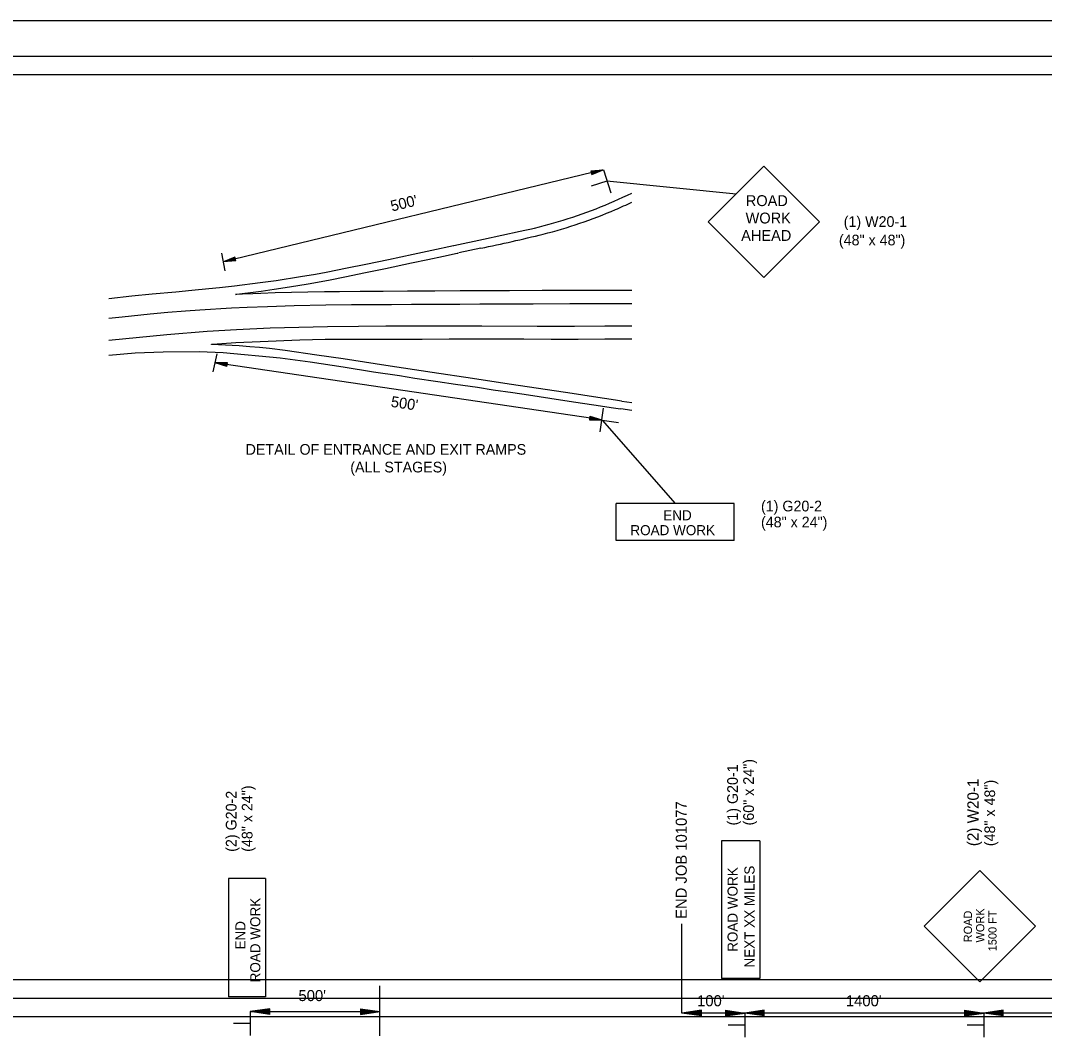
# Model space of a CAD drawing. Extents: x 13528 to 25043, y 7635 to 10612.
# Drawn here: x 14107 to 14665, y 10057 to 10612 of the extents above; entities that cross this region are included whole.
import ezdxf

# ---------------------------------------------------------------- set-up
doc = ezdxf.new("R2010")
doc.units = 0
for name, color, linetype in [('Default', 7, 'Continuous'), ('R_Border', 7, 'Continuous'), ('R_Border Plan-Plan', 7, 'Continuous'), ('R_Border Title', 7, 'Continuous'), ('R_Draft', 7, 'Continuous'), ('R_No Plot', 7, 'Continuous'), ('R_Revision Date Text', 7, 'Continuous')]:
    doc.layers.add(name, color=color, linetype=linetype)

msp = doc.modelspace()

# ---------------------------------------------------------------- linework, layer by layer
at = {"layer": 'Default'}
for p, q in [((14496.62, 10516.89), (14426.18, 10523.85)), ((14423.6, 10393.7), (14463.38, 10348.28)), ((14467.07, 10070.37), (14467.07, 10118.93)), ((14302.47, 10057.91), (14302.47, 10085.27)), ((14231.83, 10071.14), (14302.45, 10071.14)), ((14501.38, 10070.37), (14467.07, 10070.37)), ((14631.67, 10070.37), (14501.38, 10070.37)), ((14722.64, 10070.37), (14631.67, 10070.37))]:
    msp.add_line(p, q, dxfattribs=at)
for points in [[(14342.84, 10488.87), (14359.01, 10492.27), (14378.86, 10496.59)], [(14154.77, 10460.04), (14167.3, 10461.45), (14178.38, 10462.52), (14191.29, 10463.65), (14200.02, 10464.43), (14209.16, 10465.34), (14215.1, 10465.98), (14223.19, 10466.91), (14237.22, 10468.67), (14245.94, 10469.84), (14259.16, 10471.87), (14267.31, 10473.25), (14273.11, 10474.38), (14284.68, 10476.61), (14294.88, 10478.74), (14307.2, 10481.3), (14320.55, 10484.11), (14330.83, 10486.33), (14342.56, 10488.79)], [(14439.75, 10464.37), (14434.31, 10464.37), (14417.92, 10464.32), (14405.38, 10464.29), (14390.88, 10464.27), (14373.12, 10464.2), (14359.89, 10464.16), (14346.18, 10464.12), (14332.37, 10464.05), (14317.44, 10463.92), (14304.24, 10463.86), (14291.73, 10463.72), (14280.35, 10463.61), (14272.2, 10463.54), (14263.22, 10463.41), (14254.23, 10463.25), (14245.3, 10462.99), (14237.53, 10462.73), (14233.25, 10462.56), (14227.52, 10462.33), (14224.49, 10462.15), (14223.75, 10462.14), (14224.43, 10462.25), (14227.45, 10462.6), (14233.3, 10463.35), (14237.77, 10463.94), (14244.83, 10464.98), (14253.27, 10466.28), (14263.28, 10467.91), (14274.53, 10469.99), (14284.27, 10471.92), (14293.71, 10473.9), (14305.53, 10476.39), (14319.71, 10479.36), (14328.64, 10481.22), (14337.04, 10482.99), (14344.62, 10484.6), (14345.2, 10484.76)], [(14357.47, 10487.33), (14345.44, 10484.79)], [(14154.77, 10449.2), (14162.05, 10450.05), (14177.18, 10451.59), (14186.79, 10452.52), (14196.43, 10453.28), (14204.28, 10453.84), (14221.51, 10454.93), (14230.16, 10455.31), (14241.15, 10455.68), (14255.64, 10456.08), (14272.99, 10456.44), (14286.93, 10456.62), (14296.13, 10456.68), (14308.85, 10456.78), (14319.63, 10456.85), (14335.14, 10456.92), (14346, 10456.96), (14356.88, 10457.03), (14369.13, 10457.08), (14386.07, 10457.13), (14405.94, 10457.17), (14419.19, 10457.23), (14433.73, 10457.25), (14439.75, 10457.25)], [(14154.77, 10437.25), (14186.34, 10440.35), (14208.4, 10442.08), (14224.32, 10443.08), (14242.6, 10443.93), (14273.89, 10444.78), (14290.86, 10444.93), (14305.62, 10445), (14330.83, 10444.98), (14357.96, 10444.97), (14388.23, 10444.92), (14408.52, 10444.95), (14425.09, 10444.99), (14439.75, 10445)], [(14434.23, 10404.07), (14430.9, 10404.59), (14418.8, 10406.42), (14407.22, 10408.2), (14388.94, 10410.92), (14372.87, 10413.3), (14353.01, 10416.3), (14330.93, 10419.53), (14305.77, 10423.38), (14282.39, 10427.05), (14268.02, 10429.1), (14250.82, 10431.67), (14242.33, 10432.64), (14236.86, 10433.16), (14231.58, 10433.63), (14225.7, 10434.08), (14214.52, 10434.79), (14210.74, 10434.97), (14210.7, 10435.05), (14213.8, 10435.32), (14223.99, 10435.92), (14237.11, 10436.56), (14258.88, 10437.43), (14272.67, 10437.7), (14293.19, 10437.81), (14309.43, 10437.8), (14325.56, 10437.84), (14340.29, 10437.93), (14352.22, 10437.94), (14367.06, 10437.9), (14380.87, 10437.93), (14395.78, 10437.87), (14410.45, 10437.86), (14425.12, 10437.92), (14438.03, 10437.93), (14439.75, 10437.94)], [(14154.77, 10429.04), (14169.05, 10430.26), (14184.4, 10430.9), (14203.93, 10431.01), (14216.99, 10430.59), (14248.04, 10427.67), (14264.36, 10425.35), (14282.44, 10422.62), (14299.03, 10420.05), (14313.06, 10417.91), (14321.42, 10416.6), (14334.07, 10414.67), (14343.69, 10413.31), (14355.67, 10411.53), (14364.27, 10410.24), (14374.97, 10408.64), (14383.4, 10407.37), (14395.06, 10405.59), (14407.96, 10403.67), (14419.1, 10402), (14429.83, 10400.37), (14433.62, 10399.81)], [(14434.35, 10404.05), (14439.75, 10403.22)], [(14439.75, 10398.87), (14433.78, 10399.76)]]:
    msp.add_lwpolyline(points, dxfattribs=at)
for centre, major_axis, ratio, start_param, end_param in [((14299.19, 10813.8), (136.7, 298.37), 0.999173, 3.949784, 4.014407), ((14307.26, 10794.21), (311.69, 3.76), 0.99865, 5.108014, 5.139342), ((14324.08, 10755.04), (261.63, 48.54), 0.992861, 4.737589, 4.90036), ((14328.05, 10745.09), (257.87, 23.44), 0.996093, 4.869476, 5.030314), ((14159.01, 11428.79), (966.83, 149.44), 0.983429, 4.765892, 4.801526)]:
    msp.add_ellipse(centre, major_axis=major_axis, ratio=ratio, start_param=start_param, end_param=end_param, dxfattribs=at)
at = {"layer": 'R_Border'}
for p, q in [((14424.19, 10530.14), (14217.16, 10479.87)), ((14417.46, 10529.53), (14424.19, 10530.14)), ((14417.46, 10529.53), (14417.94, 10527.59)), ((14417.5, 10529.37), (14423.1, 10529.87)), ((14417.54, 10529.21), (14421.99, 10529.6)), ((14417.58, 10529.04), (14420.91, 10529.34)), ((14417.62, 10528.88), (14419.81, 10529.07)), ((14417.66, 10528.71), (14418.73, 10528.81)), ((14417.74, 10528.41), (14418.73, 10528.81)), ((14417.78, 10528.24), (14419.81, 10529.07)), ((14417.82, 10528.08), (14420.91, 10529.34)), ((14417.86, 10527.92), (14421.99, 10529.6)), ((14417.9, 10527.75), (14423.1, 10529.87)), ((14417.94, 10527.59), (14424.19, 10530.14)), ((14424.37, 10530.11), (14428.36, 10517.64)), ((14481.47, 10501.74), (14511.78, 10532.05)), ((14511.78, 10532.05), (14542.09, 10501.74)), ((14426.18, 10523.85), (14417.66, 10521.13)), ((14481.47, 10501.74), (14511.78, 10471.46)), ((14511.78, 10471.46), (14542.09, 10501.74)), ((14218.05, 10475.01), (14216.28, 10484.74)), ((14223.41, 10482.42), (14217.16, 10479.87)), ((14223.45, 10482.26), (14218.25, 10480.14)), ((14223.89, 10480.48), (14223.41, 10482.42)), ((14223.89, 10480.48), (14217.16, 10479.87)), ((14223.85, 10480.64), (14218.25, 10480.14)), ((14223.49, 10482.09), (14219.36, 10480.41)), ((14223.81, 10480.8), (14219.36, 10480.41)), ((14223.53, 10481.93), (14220.44, 10480.67)), ((14223.77, 10480.97), (14220.44, 10480.67)), ((14223.57, 10481.77), (14221.54, 10480.94)), ((14223.73, 10481.13), (14221.54, 10480.94)), ((14223.61, 10481.6), (14222.63, 10481.2)), ((14223.69, 10481.3), (14222.63, 10481.2)), ((14211.66, 10420.04), (14213.67, 10429.72)), ((14219.41, 10424.89), (14212.66, 10424.88)), ((14423.42, 10393.76), (14212.66, 10424.88)), ((14219.12, 10422.91), (14212.66, 10424.88)), ((14219.39, 10424.73), (14213.77, 10424.71)), ((14219.14, 10423.08), (14213.77, 10424.71)), ((14219.36, 10424.56), (14214.9, 10424.55)), ((14219.17, 10423.25), (14214.9, 10424.55)), ((14219.34, 10424.39), (14216, 10424.38)), ((14219.19, 10423.41), (14216, 10424.38)), ((14219.31, 10424.23), (14217.12, 10424.22)), ((14219.22, 10423.58), (14217.12, 10424.22)), ((14219.29, 10424.06), (14218.22, 10424.06)), ((14219.24, 10423.75), (14218.22, 10424.06)), ((14219.12, 10422.91), (14219.41, 10424.89)), ((14422.48, 10387.29), (14424.35, 10400.24)), ((14416.96, 10395.73), (14416.67, 10393.75)), ((14416.67, 10393.75), (14423.42, 10393.76)), ((14416.69, 10393.91), (14422.31, 10393.93)), ((14416.72, 10394.08), (14421.18, 10394.09)), ((14416.74, 10394.25), (14420.08, 10394.26)), ((14416.76, 10394.42), (14418.96, 10394.42)), ((14416.79, 10394.58), (14417.86, 10394.58)), ((14416.84, 10394.89), (14417.86, 10394.58)), ((14416.86, 10395.06), (14418.96, 10394.42)), ((14416.89, 10395.23), (14420.08, 10394.26)), ((14416.91, 10395.4), (14421.18, 10394.09)), ((14416.93, 10395.56), (14422.31, 10393.93)), ((14416.96, 10395.73), (14423.42, 10393.76)), ((14423.6, 10393.7), (14432.44, 10392.44)), ((14495.56, 10348.28), (14431.2, 10348.28)), ((14431.2, 10328.06), (14431.2, 10348.28)), ((14495.56, 10328.06), (14495.56, 10348.28)), ((14495.56, 10328.06), (14431.2, 10328.06)), ((14629.5, 10148.02), (14599.19, 10117.72)), ((14629.5, 10148.02), (14659.78, 10117.72)), ((14219.91, 10143.66), (14219.91, 10079.3)), ((14240.13, 10143.66), (14219.91, 10143.66)), ((14240.13, 10143.66), (14240.13, 10079.3)), ((14599.19, 10117.72), (14629.5, 10087.41)), ((14659.78, 10117.72), (14629.5, 10087.41)), ((14240.13, 10079.3), (14219.91, 10079.3)), ((14231.83, 10071.14), (14231.83, 10058.05)), ((14501.38, 10070.37), (14501.38, 10057.28)), ((14631.67, 10070.37), (14631.67, 10057.28)), ((14231.64, 10064.63), (14222.7, 10064.62)), ((14501.19, 10063.86), (14492.25, 10063.86)), ((14631.48, 10063.86), (14622.54, 10063.86))]:
    msp.add_line(p, q, dxfattribs=at)
at = {"layer": 'R_Border Plan-Plan'}
msp.add_line((13590.22, 10078.42), (15171.12, 10078.42), dxfattribs=at)
at = {"layer": 'R_Border Title'}
for p, q in [((14242.42, 10072.73), (14231.83, 10071.14)), ((14242.42, 10069.55), (14231.83, 10071.14)), ((14242.42, 10072.46), (14233.6, 10071.14)), ((14242.42, 10069.81), (14233.6, 10071.14)), ((14242.42, 10072.19), (14235.42, 10071.14)), ((14242.42, 10070.08), (14235.42, 10071.14)), ((14242.42, 10071.93), (14237.18, 10071.14)), ((14242.42, 10070.35), (14237.18, 10071.14)), ((14242.42, 10071.66), (14238.98, 10071.14)), ((14242.42, 10070.62), (14238.98, 10071.14)), ((14242.42, 10071.39), (14240.75, 10071.14)), ((14242.42, 10070.89), (14240.75, 10071.14)), ((14242.42, 10069.55), (14242.42, 10072.73)), ((14291.86, 10072.73), (14302.45, 10071.14)), ((14291.86, 10072.73), (14291.86, 10069.55)), ((14291.86, 10072.46), (14300.69, 10071.14)), ((14291.86, 10072.19), (14298.86, 10071.14)), ((14291.86, 10071.93), (14297.1, 10071.14)), ((14291.86, 10071.65), (14295.3, 10071.14)), ((14291.86, 10071.39), (14293.53, 10071.14)), ((14291.86, 10069.55), (14302.45, 10071.14)), ((14291.86, 10070.62), (14295.3, 10071.14)), ((14291.86, 10070.08), (14298.86, 10071.14)), ((14291.86, 10069.81), (14300.69, 10071.14)), ((14291.86, 10070.35), (14297.1, 10071.14)), ((14291.86, 10070.89), (14293.53, 10071.14)), ((14477.67, 10071.96), (14467.07, 10070.37)), ((14477.67, 10068.78), (14467.07, 10070.37)), ((14477.67, 10071.7), (14468.84, 10070.37)), ((14477.67, 10069.05), (14468.84, 10070.37)), ((14477.67, 10071.43), (14470.67, 10070.37)), ((14477.67, 10069.32), (14470.67, 10070.37)), ((14477.67, 10071.16), (14472.43, 10070.37)), ((14477.67, 10069.58), (14472.43, 10070.37)), ((14477.67, 10070.89), (14474.23, 10070.37)), ((14477.67, 10069.86), (14474.23, 10070.37)), ((14477.67, 10070.62), (14475.99, 10070.37)), ((14477.67, 10070.12), (14475.99, 10070.37)), ((14477.67, 10068.78), (14477.67, 10071.96)), ((14490.78, 10071.96), (14501.38, 10070.37)), ((14490.78, 10071.96), (14490.78, 10068.78)), ((14490.78, 10071.7), (14499.61, 10070.37)), ((14490.78, 10071.43), (14497.79, 10070.37)), ((14490.78, 10071.16), (14496.02, 10070.37)), ((14490.78, 10070.89), (14494.23, 10070.37)), ((14490.78, 10070.62), (14492.46, 10070.37)), ((14490.78, 10068.78), (14501.38, 10070.37)), ((14490.78, 10069.85), (14494.23, 10070.37)), ((14490.78, 10069.32), (14497.79, 10070.37)), ((14490.78, 10069.05), (14499.61, 10070.37)), ((14490.78, 10069.58), (14496.02, 10070.37)), ((14490.78, 10070.12), (14492.46, 10070.37)), ((14511.97, 10071.96), (14501.38, 10070.37)), ((14511.97, 10068.78), (14501.38, 10070.37)), ((14511.97, 10071.7), (14503.15, 10070.37)), ((14511.97, 10069.05), (14503.15, 10070.37)), ((14511.97, 10071.43), (14504.97, 10070.37)), ((14511.97, 10069.32), (14504.97, 10070.37)), ((14511.97, 10071.16), (14506.73, 10070.37)), ((14511.97, 10069.58), (14506.73, 10070.37)), ((14511.97, 10070.89), (14508.53, 10070.37)), ((14511.97, 10069.86), (14508.53, 10070.37)), ((14511.97, 10070.62), (14510.3, 10070.37)), ((14511.97, 10070.12), (14510.3, 10070.37)), ((14511.97, 10068.78), (14511.97, 10071.96)), ((14621.07, 10071.96), (14631.67, 10070.37)), ((14621.07, 10071.96), (14621.07, 10068.78)), ((14621.07, 10071.7), (14629.9, 10070.37)), ((14621.07, 10071.43), (14628.08, 10070.37)), ((14621.07, 10071.16), (14626.31, 10070.37)), ((14621.07, 10070.89), (14624.52, 10070.37)), ((14621.07, 10070.62), (14622.75, 10070.37)), ((14621.07, 10068.78), (14631.67, 10070.37)), ((14621.07, 10069.85), (14624.52, 10070.37)), ((14621.07, 10069.32), (14628.08, 10070.37)), ((14621.07, 10069.05), (14629.9, 10070.37)), ((14621.07, 10069.58), (14626.31, 10070.37)), ((14621.07, 10070.12), (14622.75, 10070.37)), ((14642.26, 10071.96), (14631.67, 10070.37)), ((14642.26, 10068.78), (14631.67, 10070.37)), ((14642.26, 10071.7), (14633.44, 10070.37)), ((14642.26, 10069.05), (14633.44, 10070.37)), ((14642.26, 10071.43), (14635.26, 10070.37)), ((14642.26, 10069.32), (14635.26, 10070.37)), ((14642.26, 10071.16), (14637.02, 10070.37)), ((14642.26, 10069.58), (14637.02, 10070.37)), ((14642.26, 10070.89), (14638.82, 10070.37)), ((14642.26, 10069.86), (14638.82, 10070.37)), ((14642.26, 10070.62), (14640.59, 10070.37)), ((14642.26, 10070.12), (14640.59, 10070.37)), ((14642.26, 10068.78), (14642.26, 10071.96))]:
    msp.add_line(p, q, dxfattribs=at)
at = {"layer": 'R_Draft'}
for p, q in [((13590.22, 10592.07), (15171.12, 10592.07)), ((14352.82, 10590.77), (14352.82, 10590.77)), ((14352.82, 10590.77), (14352.82, 10590.77))]:
    msp.add_line(p, q, dxfattribs=at)
at = {"layer": 'R_No Plot'}
for p, q in [((14488.63, 10164.19), (14488.63, 10089.15)), ((14509.5, 10164.19), (14488.63, 10164.19)), ((14509.5, 10164.19), (14509.5, 10089.15)), ((14509.5, 10089.15), (14488.63, 10089.15))]:
    msp.add_line(p, q, dxfattribs=at)
at = {"layer": 'R_Revision Date Text'}
for points in [[(13528.19, 10611.55), (15194.89, 10611.55), (15194.89, 9544.86), (13528.19, 9544.86)], [(15161.12, 10088.42), (13600.22, 10088.42), (13600.22, 10582.07), (14847.92, 10582.07), (14847.92, 10532.67), (14935.62, 10532.67), (15056.12, 10532.67), (15056.12, 10421.01), (15161.12, 10421.01)], [(13600.22, 10582.07), (14847.92, 10582.07), (14847.92, 10532.67), (14935.62, 10532.67), (15056.12, 10532.67), (15056.12, 10421.01), (15161.12, 10421.01), (15161.12, 9574.77), (13600.22, 9574.77)], [(13600.22, 10068.42), (15161.12, 10068.42), (15161.12, 9574.77), (13600.22, 9574.77)]]:
    msp.add_lwpolyline(points, close=True, dxfattribs=at)

# ---------------------------------------------------------------- texts
at = {"layer": 'Default'}
for s, height, p in [('DETAIL OF ENTRANCE AND EXIT RAMPS', 5.814, (14229.27, 10374.79)), ('(ALL STAGES)', 5.814, (14286.31, 10365.14)), ("500'", 6.031, (14258.07, 10076.9)), ("100'", 6.031, (14475.34, 10074.07)), ("1400'", 6.031, (14556.45, 10074.07))]:
    msp.add_text(s, height=height, dxfattribs=at).set_placement(p)
msp.add_text('END JOB 101077', height=6.0315, rotation=90, dxfattribs=at).set_placement((14469.72, 10121.71))
at = {"layer": 'R_Border'}
for s, height, rotation, p in [("500'", 5.933, 13.6464, (14309.07, 10507.35)), ('ROAD', 5.933, 359.9996, (14501.9, 10510.35)), ('WORK', 5.933, 359.9996, (14501.78, 10500.86)), ('(1) W20-1', 5.815, 360, (14555.26, 10498.99)), ('AHEAD', 5.933, 359.9996, (14499.37, 10491.36)), ('(48" x 48")', 5.8146, 360, (14552.64, 10488.92)), ("500'", 5.933, 351.6023, (14308.17, 10400.95)), ('(1) G20-1', 5.815, 90, (14497.58, 10172.67)), ('(60" x 24")', 5.814, 90, (14506.3, 10172.67)), ('(2) W20-1', 6.202, 90, (14628.85, 10161.36)), ('(48" x 24")', 5.814, 90, (14233.01, 10158.28)), ('(48" x 48")', 5.814, 90, (14637.78, 10161.36)), ('(2) G20-2', 5.815, 90, (14224.3, 10158.28)), ('ROAD WORK', 5.495, 90, (14497.43, 10103.74)), ('NEXT XX MILES', 5.4947, 90, (14506.64, 10095.21)), ('ROAD WORK', 5.495, 90, (14237.28, 10087.09)), ('ROAD', 4.465, 90.0004, (14625.18, 10108.96)), ('WORK', 4.464, 90, (14631.88, 10108.87)), ('1500 FT', 4.465, 90.0006, (14638.58, 10104.06)), ('END', 5.495, 90, (14229.16, 10105.02))]:
    msp.add_text(s, height=height, rotation=rotation, dxfattribs=at).set_placement(p)
for s, height, p in [('(1) G20-2', 5.815, (14510.17, 10343.9)), ('END', 5.495, (14456.92, 10339.03)), ('(48" x 24")', 5.814, (14510.17, 10335.18)), ('ROAD WORK', 5.495, (14438.99, 10330.91))]:
    msp.add_text(s, height=height, dxfattribs=at).set_placement(p)

doc.saveas('drawing.dxf')
